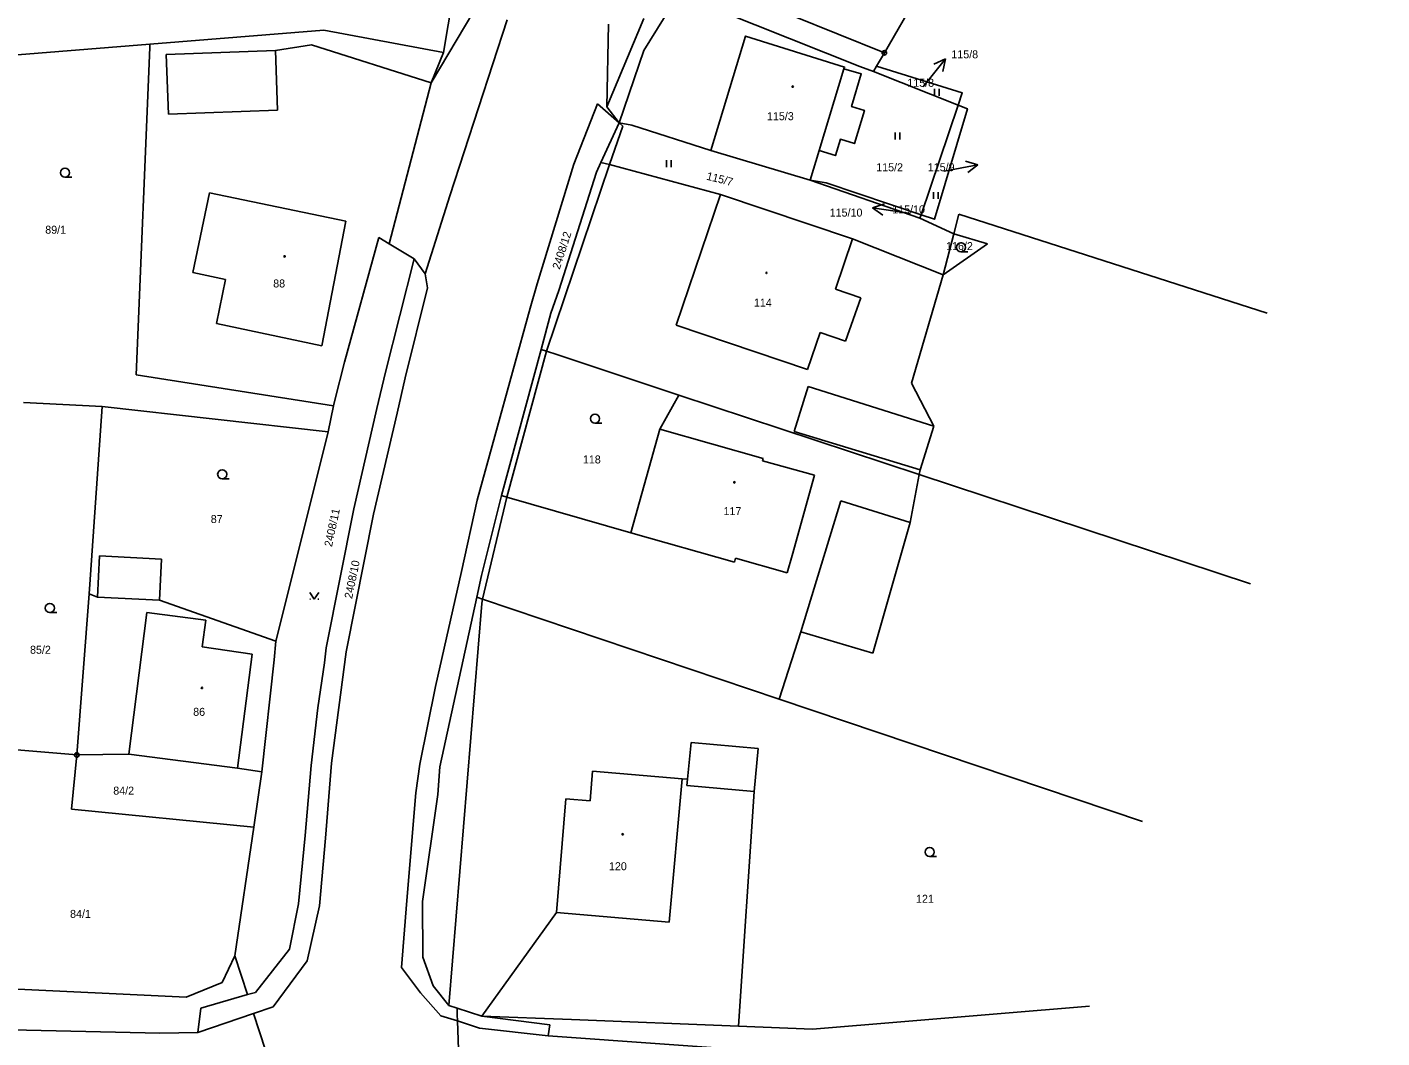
# Model space of a CAD drawing. Extents: x -454285 to -453563, y -1108687 to -1108249.
# Drawn here: x -453681.8 to -453563.3, y -1108476.5 to -1108388.1 of the extents above; entities that cross this region are included whole.
import ezdxf

# ---------------------------------------------------------------- set-up
doc = ezdxf.new("R2010")
doc.units = 0
for name, color, linetype in [('1', 7, 'Continuous'), ('13', 7, 'Continuous'), ('14', 7, 'Continuous'), ('15', 7, 'Continuous'), ('16', 7, 'Continuous'), ('2', 7, 'Continuous'), ('23', 7, 'Continuous'), ('25', 7, 'Continuous'), ('28', 7, 'Continuous')]:
    doc.layers.add(name, color=color, linetype=linetype)

# ---------------------------------------------------------------- blocks, each defined once
blk = doc.blocks.new('Z402')
for start, end in [(0, 180), (180, 0)]:
    blk.add_arc((0, 0), 0.15, start, end)
blk = doc.blocks.new('Z105')
for radius in [0.5, 0.01]:
    blk.add_circle((0, 0), radius)
blk = doc.blocks.new('Z3040')
blk.add_line((1.5, 0), (0, 0))
blk.add_circle((0, 1), 1)
blk = doc.blocks.new('Z3060')
for p, q in [((-0.5, 1.5), (-0.5, 0)), ((0.5, 1.5), (0.5, 0))]:
    blk.add_line(p, q)
blk = doc.blocks.new('Z3140')
for p, q in [((-1, 1.5), (0, 0)), ((-1, 0), (-0.8, 0)), ((0, 0), (1, 1.5)), ((0.8, 0), (1, 0))]:
    blk.add_line(p, q)
blk = doc.blocks.new('Z61')
for p, q in [((0, 3), (-0.5, 2)), ((0, 0), (0, 3)), ((0, 3), (0.5, 2))]:
    blk.add_line(p, q)

msp = doc.modelspace()

# ---------------------------------------------------------------- linework, layer by layer
at = {"layer": '1'}
for p, q in [((-453643.59, -1108379.6), (-453645.41, -1108390.3)), ((-453640.43, -1108382.75), (-453646.47, -1108392.95)), ((-453623.75, -1108383.5), (-453606.84, -1108390.34)), ((-453606.84, -1108390.34), (-453602.66, -1108383.15)), ((-453627.89, -1108390.14), (-453624.82, -1108385.22)), ((-453624.82, -1108385.22), (-453608.97, -1108391.55)), ((-453631.13, -1108395.05), (-453630.96, -1108387.82)), ((-453655.87, -1108388.36), (-453671.08, -1108389.58)), ((-453645.41, -1108390.3), (-453655.87, -1108388.36)), ((-453671.08, -1108389.58), (-453685.01, -1108390.71)), ((-453672.28, -1108418.51), (-453671.1, -1108389.86)), ((-453671.1, -1108389.86), (-453671.08, -1108389.58)), ((-453630.05, -1108396.45), (-453627.89, -1108390.14)), ((-453646.47, -1108392.95), (-453645.41, -1108390.3)), ((-453607.52, -1108391.51), (-453606.84, -1108390.34)), ((-453608.97, -1108391.55), (-453607.78, -1108391.96)), ((-453607.78, -1108391.96), (-453607.52, -1108391.51)), ((-453600.38, -1108394.91), (-453607.78, -1108391.96)), ((-453650.16, -1108407.03), (-453646.47, -1108392.95)), ((-453634.01, -1108400.07), (-453631.93, -1108394.8)), ((-453631.93, -1108394.8), (-453630.05, -1108396.45)), ((-453603.63, -1108404.5), (-453600.38, -1108394.91)), ((-453631.13, -1108395.05), (-453630.05, -1108396.45)), ((-453631.64, -1108399.92), (-453630.05, -1108396.45)), ((-453622.01, -1108398.87), (-453613.32, -1108401.49)), ((-453612.53, -1108398.89), (-453613.32, -1108401.49)), ((-453637.22, -1108410.53), (-453634.01, -1108400.07)), ((-453632.03, -1108400.79), (-453635.3, -1108411.13)), ((-453632.03, -1108400.79), (-453631.64, -1108399.92)), ((-453631.64, -1108399.92), (-453631.26, -1108400.02)), ((-453631.26, -1108400.02), (-453630.87, -1108400.12)), ((-453630.87, -1108400.12), (-453621.18, -1108402.72)), ((-453613.32, -1108401.49), (-453603.73, -1108404.81)), ((-453621.18, -1108402.72), (-453609.64, -1108406.61)), ((-453603.73, -1108404.81), (-453603.63, -1108404.5)), ((-453603.73, -1108404.81), (-453600.76, -1108406.17)), ((-453600.31, -1108404.45), (-453600.76, -1108406.17)), ((-453573.35, -1108413.12), (-453600.31, -1108404.45)), ((-453651.05, -1108406.49), (-453654.06, -1108417.38)), ((-453651.05, -1108406.49), (-453650.16, -1108407.03)), ((-453609.64, -1108406.61), (-453601.7, -1108409.74)), ((-453600.76, -1108406.17), (-453601.7, -1108409.74)), ((-453600.76, -1108406.17), (-453597.82, -1108407.05)), ((-453650.16, -1108407.03), (-453647.98, -1108408.35)), ((-453597.82, -1108407.05), (-453601.7, -1108409.74)), ((-453650.48, -1108418.28), (-453647.98, -1108408.35)), ((-453647.98, -1108408.35), (-453647, -1108409.66)), ((-453647, -1108409.66), (-453646.79, -1108410.88)), ((-453601.7, -1108409.74), (-453604.46, -1108419.23)), ((-453646.79, -1108410.88), (-453648.75, -1108418.76)), ((-453637.83, -1108412.67), (-453637.22, -1108410.53)), ((-453635.3, -1108411.13), (-453636.01, -1108413.11)), ((-453642.45, -1108429.45), (-453637.83, -1108412.67)), ((-453636.87, -1108416.28), (-453636.01, -1108413.11)), ((-453640.32, -1108429.06), (-453636.87, -1108416.28)), ((-453636.87, -1108416.28), (-453636.38, -1108416.44)), ((-453654.06, -1108417.38), (-453654.92, -1108420.71)), ((-453636.38, -1108416.44), (-453635.5, -1108416.73)), ((-453624.81, -1108420.27), (-453635.5, -1108416.73)), ((-453672.28, -1108418.51), (-453655.02, -1108421.22)), ((-453651.23, -1108421.45), (-453650.48, -1108418.28)), ((-453648.75, -1108418.76), (-453649.47, -1108421.84)), ((-453604.46, -1108419.23), (-453602.5, -1108422.99)), ((-453682.13, -1108420.92), (-453675.26, -1108421.26)), ((-453654.92, -1108420.71), (-453655.02, -1108421.22)), ((-453626.47, -1108423.26), (-453624.81, -1108420.27)), ((-453624.81, -1108420.27), (-453603.79, -1108427.21)), ((-453675.28, -1108421.7), (-453676.39, -1108437.64)), ((-453675.26, -1108421.26), (-453675.28, -1108421.7)), ((-453655.49, -1108423.49), (-453675.26, -1108421.26)), ((-453655.02, -1108421.22), (-453655.49, -1108423.49)), ((-453653.26, -1108430.21), (-453651.23, -1108421.45)), ((-453649.47, -1108421.84), (-453651.53, -1108430.69)), ((-453629.03, -1108432.31), (-453626.47, -1108423.26)), ((-453602.5, -1108422.99), (-453603.7, -1108426.81)), ((-453655.6, -1108423.98), (-453660.08, -1108441.78)), ((-453655.49, -1108423.49), (-453655.6, -1108423.98)), ((-453603.7, -1108426.81), (-453603.79, -1108427.21)), ((-453604.59, -1108431.41), (-453603.79, -1108427.21)), ((-453603.79, -1108427.21), (-453574.82, -1108436.79)), ((-453640.57, -1108429.97), (-453640.32, -1108429.06)), ((-453640.32, -1108429.06), (-453639.87, -1108429.19)), ((-453639.87, -1108429.19), (-453629.03, -1108432.31)), ((-453655.66, -1108442.37), (-453653.26, -1108430.21)), ((-453643.84, -1108435.69), (-453642.45, -1108429.45)), ((-453642.07, -1108436.04), (-453640.57, -1108429.97)), ((-453651.53, -1108430.69), (-453653.93, -1108442.72)), ((-453604.59, -1108431.41), (-453607.85, -1108442.84)), ((-453675.67, -1108437.94), (-453675.49, -1108434.34)), ((-453675.49, -1108434.34), (-453670.08, -1108434.61)), ((-453670.08, -1108434.61), (-453670.26, -1108438.21)), ((-453646.1, -1108445.75), (-453643.84, -1108435.69)), ((-453642.07, -1108436.04), (-453642.48, -1108437.94)), ((-453676.39, -1108437.64), (-453677.48, -1108451.74)), ((-453676.39, -1108437.64), (-453675.67, -1108437.94)), ((-453670.26, -1108438.21), (-453660.08, -1108441.78)), ((-453642.48, -1108437.94), (-453645.72, -1108452.78)), ((-453641.98, -1108438.11), (-453642.48, -1108437.94)), ((-453616.04, -1108446.85), (-453641.98, -1108438.11)), ((-453614.15, -1108440.98), (-453616.04, -1108446.85)), ((-453607.85, -1108442.84), (-453614.15, -1108440.98)), ((-453660.08, -1108441.78), (-453660.23, -1108443.41)), ((-453655.82, -1108443.69), (-453655.66, -1108442.37)), ((-453661.29, -1108453.23), (-453660.23, -1108443.41)), ((-453653.93, -1108442.72), (-453655.21, -1108452.46)), ((-453656.41, -1108447.61), (-453655.82, -1108443.69)), ((-453646.1, -1108445.75), (-453647.48, -1108452.56)), ((-453584.26, -1108457.55), (-453616.04, -1108446.85)), ((-453656.97, -1108452.66), (-453656.41, -1108447.61)), ((-453624.07, -1108453.87), (-453623.75, -1108450.64)), ((-453623.75, -1108450.64), (-453617.89, -1108451.17)), ((-453677.48, -1108451.74), (-453684.51, -1108451.15)), ((-453677.93, -1108456.48), (-453677.48, -1108451.74)), ((-453677.48, -1108451.74), (-453672.94, -1108451.68)), ((-453672.94, -1108451.68), (-453663.43, -1108452.89)), ((-453617.89, -1108451.17), (-453618.23, -1108454.95)), ((-453663.43, -1108452.89), (-453661.29, -1108453.23)), ((-453657.49, -1108458.79), (-453656.97, -1108452.66)), ((-453655.21, -1108452.46), (-453655.73, -1108459.02)), ((-453647.82, -1108455.05), (-453647.48, -1108452.56)), ((-453645.72, -1108452.78), (-453645.91, -1108455.19)), ((-453661.99, -1108458.06), (-453661.29, -1108453.23)), ((-453632.58, -1108455.75), (-453632.37, -1108453.17)), ((-453632.37, -1108453.17), (-453624.52, -1108453.83)), ((-453624.52, -1108453.83), (-453624.07, -1108453.87)), ((-453648.62, -1108464.48), (-453647.82, -1108455.05)), ((-453645.91, -1108455.19), (-453647.24, -1108464.56)), ((-453618.23, -1108454.95), (-453619.6, -1108475.47)), ((-453661.99, -1108458.06), (-453677.93, -1108456.48)), ((-453635.53, -1108465.52), (-453634.7, -1108455.57)), ((-453634.7, -1108455.57), (-453632.58, -1108455.75)), ((-453663.65, -1108469.32), (-453661.99, -1108458.06)), ((-453658.08, -1108464.77), (-453657.49, -1108458.79)), ((-453655.73, -1108459.02), (-453656.25, -1108464.94)), ((-453658.86, -1108468.71), (-453658.08, -1108464.77)), ((-453649.07, -1108470.32), (-453648.62, -1108464.48)), ((-453647.24, -1108464.56), (-453647.21, -1108469.41)), ((-453656.25, -1108464.94), (-453657.34, -1108469.74)), ((-453635.53, -1108465.52), (-453642.04, -1108474.57)), ((-453663.65, -1108469.32), (-453664.75, -1108471.65)), ((-453663.65, -1108469.32), (-453662.55, -1108472.7)), ((-453661.85, -1108472.5), (-453658.86, -1108468.71)), ((-453647.21, -1108469.41), (-453646.3, -1108471.92)), ((-453657.34, -1108469.74), (-453660.31, -1108473.76)), ((-453647.41, -1108472.53), (-453649.07, -1108470.32)), ((-453664.75, -1108471.65), (-453667.9, -1108472.91)), ((-453646.3, -1108471.92), (-453644.95, -1108473.65)), ((-453667.9, -1108472.91), (-453686.52, -1108472.05)), ((-453662.55, -1108472.7), (-453666.63, -1108473.87)), ((-453661.85, -1108472.5), (-453662.55, -1108472.7)), ((-453645.63, -1108474.54), (-453647.41, -1108472.53)), ((-453666.88, -1108476), (-453666.63, -1108473.87)), ((-453666.88, -1108476), (-453662.02, -1108474.34)), ((-453662.02, -1108474.34), (-453660.31, -1108473.76)), ((-453662.02, -1108474.34), (-453658.66, -1108484.7)), ((-453644.95, -1108473.65), (-453644.22, -1108473.88)), ((-453644.22, -1108473.88), (-453642.04, -1108474.57)), ((-453644.22, -1108473.88), (-453644.2, -1108474.46)), ((-453588.88, -1108473.71), (-453613.12, -1108475.73)), ((-453645.63, -1108474.54), (-453644.18, -1108475)), ((-453644.2, -1108474.46), (-453644.18, -1108475)), ((-453644.18, -1108475), (-453643.88, -1108483.45)), ((-453634.22, -1108474.87), (-453642.04, -1108474.57)), ((-453619.6, -1108475.47), (-453634.22, -1108474.87)), ((-453613.12, -1108475.73), (-453619.6, -1108475.47))]:
    msp.add_line(p, q, dxfattribs=at)
for points in [[(-453622.01, -1108398.87), (-453618.98, -1108388.88), (-453610.32, -1108391.58), (-453610.37, -1108391.73)], [(-453610.37, -1108391.73), (-453608.86, -1108392.19), (-453609.71, -1108395.04), (-453608.59, -1108395.38), (-453609.46, -1108398.27), (-453610.69, -1108397.9), (-453611.12, -1108399.32), (-453612.53, -1108398.89)], [(-453600.38, -1108394.91), (-453600.02, -1108393.85), (-453607.52, -1108391.51)], [(-453603.63, -1108404.5), (-453602.44, -1108404.9), (-453599.57, -1108395.23), (-453600.38, -1108394.91)], [(-453630.05, -1108396.45), (-453628.94, -1108396.68), (-453622.01, -1108398.87)], [(-453613.32, -1108401.49), (-453611.93, -1108401.72), (-453603.63, -1108404.5)]]:
    msp.add_lwpolyline(points, dxfattribs=at)
at = {"layer": '13'}
for p, q in [((-453603.43, -1108393.31), (-453603.36, -1108393.21)), ((-453601.64, -1108400.69), (-453601.6, -1108400.69)), ((-453604.58, -1108404.38), (-453604.91, -1108404.33)), ((-453600.04, -1108407.59), (-453600.01, -1108407.61))]:
    msp.add_line(p, q, dxfattribs=at)
at = {"layer": '2'}
for p, q in [((-453639.84, -1108387.45), (-453644.86, -1108402.86)), ((-453627.88, -1108387.34), (-453631.13, -1108395.05)), ((-453669.65, -1108390.5), (-453660.11, -1108390.14)), ((-453660.11, -1108390.14), (-453656.94, -1108389.65)), ((-453660.11, -1108390.14), (-453659.92, -1108395.34)), ((-453656.94, -1108389.65), (-453646.47, -1108392.95)), ((-453669.45, -1108395.7), (-453669.65, -1108390.5)), ((-453612.53, -1108398.89), (-453610.37, -1108391.73)), ((-453659.92, -1108395.34), (-453669.45, -1108395.7)), ((-453629.73, -1108396.74), (-453630.87, -1108400.12)), ((-453629.73, -1108396.74), (-453630.05, -1108396.45)), ((-453630.87, -1108400.12), (-453636.38, -1108416.44)), ((-453665.86, -1108402.57), (-453667.33, -1108409.55)), ((-453665.86, -1108402.57), (-453653.96, -1108405.07)), ((-453647, -1108409.66), (-453644.86, -1108402.86)), ((-453625.04, -1108414.17), (-453621.18, -1108402.72)), ((-453653.96, -1108405.07), (-453656.05, -1108415.95)), ((-453609.64, -1108406.61), (-453611.12, -1108411.01)), ((-453667.33, -1108409.55), (-453664.46, -1108410.15)), ((-453664.46, -1108410.15), (-453665.27, -1108414.01)), ((-453611.12, -1108411.01), (-453608.91, -1108411.76)), ((-453608.91, -1108411.76), (-453610.24, -1108415.56)), ((-453665.27, -1108414.01), (-453656.05, -1108415.95)), ((-453613.55, -1108418.04), (-453625.04, -1108414.17)), ((-453613.55, -1108418.04), (-453612.46, -1108414.81)), ((-453610.24, -1108415.56), (-453612.46, -1108414.81)), ((-453639.87, -1108429.19), (-453636.38, -1108416.44)), ((-453613.5, -1108419.53), (-453614.73, -1108423.44)), ((-453602.5, -1108422.99), (-453613.5, -1108419.53)), ((-453626.47, -1108423.26), (-453617.43, -1108425.82)), ((-453614.73, -1108423.44), (-453603.7, -1108426.81)), ((-453617.43, -1108425.82), (-453617.49, -1108426.02)), ((-453617.49, -1108426.02), (-453612.95, -1108427.28)), ((-453612.95, -1108427.28), (-453614.91, -1108434.3)), ((-453641.98, -1108438.11), (-453639.87, -1108429.19)), ((-453614.15, -1108440.98), (-453610.65, -1108429.51)), ((-453610.65, -1108429.51), (-453604.59, -1108431.41)), ((-453629.03, -1108432.31), (-453619.94, -1108434.88)), ((-453619.85, -1108434.54), (-453619.94, -1108434.88)), ((-453619.85, -1108434.54), (-453615.33, -1108435.8)), ((-453615.33, -1108435.8), (-453614.91, -1108434.3)), ((-453675.67, -1108437.94), (-453670.26, -1108438.21)), ((-453644.95, -1108473.65), (-453642.06, -1108438.49)), ((-453642.06, -1108438.49), (-453641.98, -1108438.11)), ((-453672.94, -1108451.68), (-453671.36, -1108439.28)), ((-453671.36, -1108439.28), (-453666.2, -1108439.94)), ((-453666.2, -1108439.94), (-453666.5, -1108442.29)), ((-453666.5, -1108442.29), (-453662.15, -1108442.92)), ((-453662.15, -1108442.92), (-453663.43, -1108452.89)), ((-453624.52, -1108453.83), (-453625.65, -1108466.35)), ((-453624.07, -1108453.87), (-453624.13, -1108454.42)), ((-453624.13, -1108454.42), (-453618.23, -1108454.95)), ((-453635.53, -1108465.52), (-453625.65, -1108466.35)), ((-453670.23, -1108476.06), (-453858.46, -1108471.89)), ((-453642.24, -1108475.62), (-453644.18, -1108475)), ((-453636.11, -1108475.35), (-453642.04, -1108474.57)), ((-453636.11, -1108475.35), (-453636.26, -1108476.29)), ((-453666.88, -1108476), (-453670.23, -1108476.06)), ((-453636.26, -1108476.29), (-453642.24, -1108475.62)), ((-453563.32, -1108481.51), (-453636.26, -1108476.29))]:
    msp.add_line(p, q, dxfattribs=at)

# ---------------------------------------------------------------- block references
at = {"layer": '16'}
for p, rotation in [((-453603.36, -1108393.21), -38.7491), ((-453601.6, -1108400.69), -79.24540000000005), ((-453604.91, -1108404.33), 81.4082)]:
    msp.add_blockref('Z61', p, dxfattribs=dict(at, rotation=rotation))
at = {"layer": '23', "xscale": 0.4, "yscale": 0.4000000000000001}
for name, p in [('Z3060', (-453602.25, -1108394.09)), ('Z3060', (-453605.7, -1108397.91)), ('Z3040', (-453678.51, -1108401.22)), ('Z3060', (-453625.7, -1108400.34)), ('Z3060', (-453602.33, -1108403.12)), ('Z3040', (-453600.13, -1108407.75)), ('Z3040', (-453632.15, -1108422.73)), ('Z3040', (-453664.76, -1108427.6)), ('Z3140', (-453656.71, -1108438.12)), ('Z3040', (-453679.84, -1108439.29)), ('Z3040', (-453602.88, -1108460.63))]:
    msp.add_blockref(name, p, dxfattribs=at)
at = {"layer": '25', "xscale": 0.4, "yscale": 0.4000000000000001}
for p in [(-453614.86, -1108393.29), (-453659.3, -1108408.14), (-453617.15, -1108409.58), (-453619.95, -1108427.9), (-453666.54, -1108445.88), (-453629.73, -1108458.67)]:
    msp.add_blockref('Z402', p, dxfattribs=at)
at = {"layer": '28', "xscale": 0.4, "yscale": 0.4000000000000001}
for p in [(-453606.84, -1108390.34), (-453677.48, -1108451.74)]:
    msp.add_blockref('Z105', p, dxfattribs=at)

# ---------------------------------------------------------------- texts
at = {"layer": '14'}
for s, p in [('115/8', (-453604.83, -1108393.31)), ('115/2', (-453607.55, -1108400.7)), ('115/9', (-453603.04, -1108400.69)), ('115/10', (-453606.15, -1108404.38)), ('89/1', (-453680.24, -1108406.16)), ('116/2', (-453601.44, -1108407.59)), ('118', (-453633.21, -1108426.25)), ('87', (-453665.76, -1108431.46)), ('85/2', (-453681.57, -1108442.89)), ('84/2', (-453674.29, -1108455.21)), ('121', (-453604.07, -1108464.67)), ('84/1', (-453678.07, -1108465.99))]:
    msp.add_text(s, height=0.7, dxfattribs=at).set_placement(p)
for s, rotation, p in [('115/7', 345.7971, (-453622.45, -1108401.42)), ('2408/12', 72.189, (-453635.24, -1108409.33)), ('2408/11', 78.039, (-453655.16, -1108433.58)), ('2408/10', 78.381, (-453653.4, -1108438.12))]:
    msp.add_text(s, height=0.7, rotation=rotation, dxfattribs=at).set_placement(p)
at = {"layer": '15'}
for s, p in [('115/3', (-453617.11, -1108396.23)), ('88', (-453660.3, -1108410.86)), ('114', (-453618.25, -1108412.54)), ('117', (-453620.91, -1108430.77)), ('86', (-453667.3, -1108448.32)), ('120', (-453630.93, -1108461.82))]:
    msp.add_text(s, height=0.7, dxfattribs=at).set_placement(p)
at = {"layer": '16'}
for s, p in [('115/8', (-453600.98, -1108390.82)), ('115/10', (-453611.62, -1108404.66))]:
    msp.add_text(s, height=0.7, dxfattribs=at).set_placement(p)

doc.saveas('drawing.dxf')
